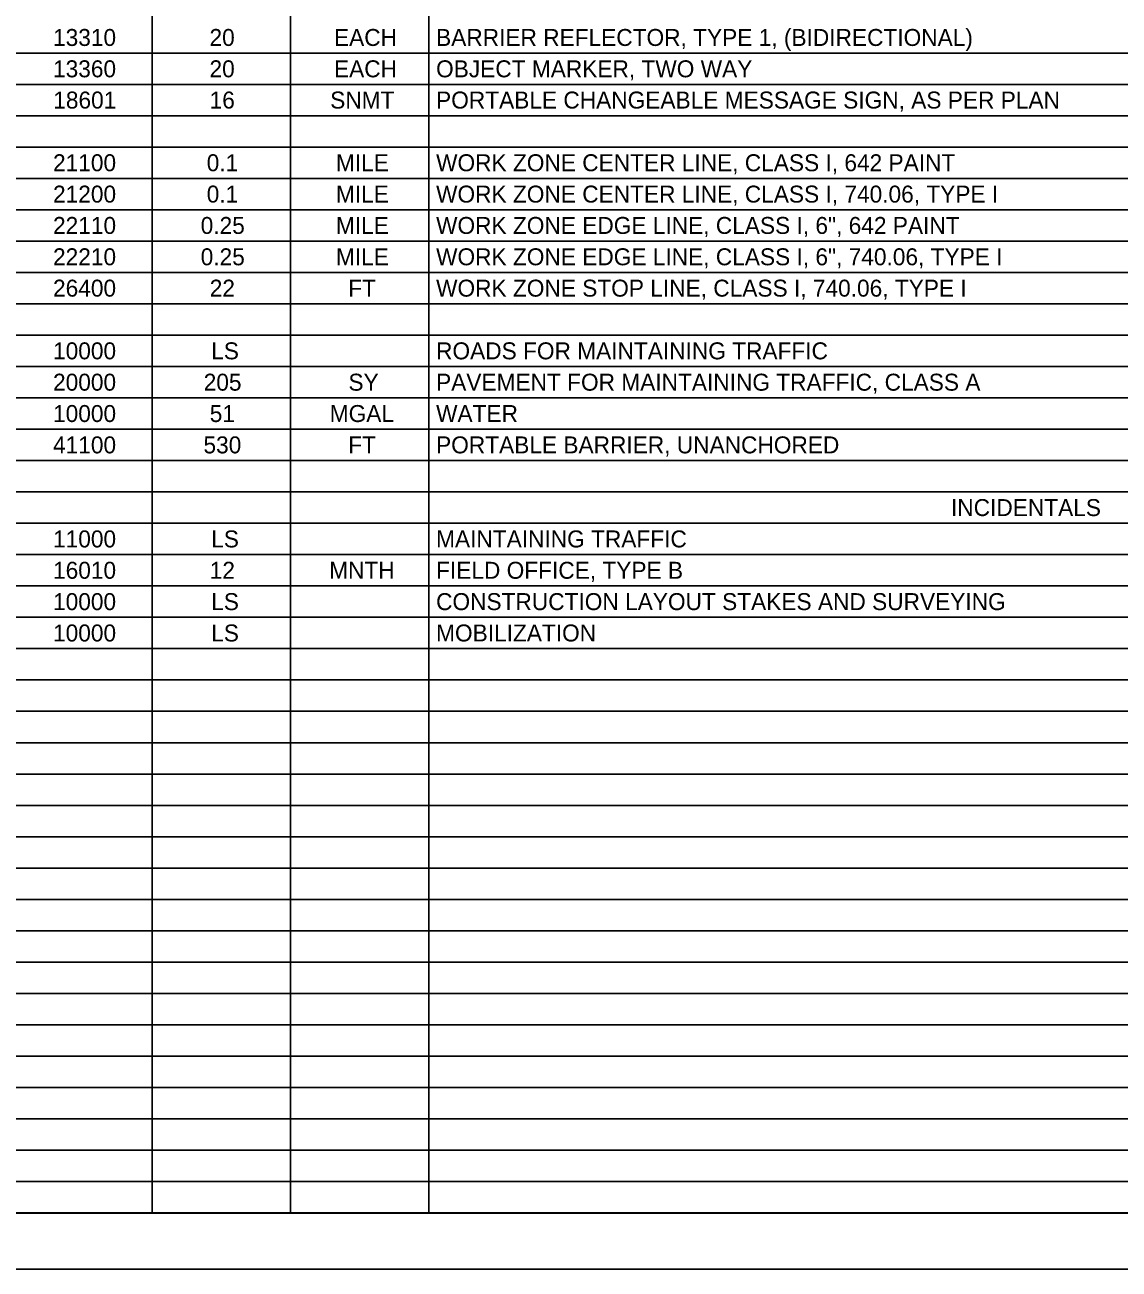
# Model space of a CAD drawing. Extents: x 0 to 34, y 0 to 22.
# Drawn here: x 16.9 to 26.67, y 0 to 11.11 of the extents above; entities that cross this region are included whole.
import ezdxf

# ---------------------------------------------------------------- set-up
doc = ezdxf.new("R2010")
doc.units = 0
for name, color, linetype in [('SH_Border', 7, 'Continuous'), ('SH_Cut_Line', 7, 'Continuous'), ('SH_Text', 7, 'Continuous')]:
    doc.layers.add(name, color=color, linetype=linetype)

msp = doc.modelspace()

# ---------------------------------------------------------------- linework, layer by layer
at = {"layer": 'SH_Border'}
msp.add_lwpolyline([(1.5, 21.5), (33.5, 21.5), (33.5, 0.5), (1.5, 0.5)], close=True, dxfattribs=at)
at = {"layer": 'SH_Cut_Line'}
msp.add_lwpolyline([(0, 0), (34, 0), (34, 22), (0, 22)], close=True, dxfattribs=at)
at = {"layer": 'SH_Text'}
for p, q in [((18.035, 21.5), (18.035, 0.502)), ((19.27, 21.5), (19.27, 0.502)), ((20.505, 21.5), (20.505, 0.502)), ((1.5, 10.861), (32, 10.861)), ((1.5, 10.581), (32, 10.581)), ((1.5, 10.301), (32, 10.301)), ((1.5, 10.021), (32, 10.021)), ((1.5, 9.741), (32, 9.741)), ((1.5, 9.461), (32, 9.461)), ((1.5, 9.181), (32, 9.181)), ((1.5, 8.901), (32, 8.901)), ((1.5, 8.621), (32, 8.621)), ((1.5, 8.342), (32, 8.342)), ((1.5, 8.062), (32, 8.062)), ((1.5, 7.782), (32, 7.782)), ((1.5, 7.502), (32, 7.502)), ((1.5, 7.222), (32, 7.222)), ((1.5, 6.942), (32, 6.942)), ((1.5, 6.662), (32, 6.662)), ((1.5, 6.382), (32, 6.382)), ((1.5, 6.102), (32, 6.102)), ((1.5, 5.822), (32, 5.822)), ((1.5, 5.542), (32, 5.542)), ((1.5, 5.262), (32, 5.262)), ((1.5, 4.982), (32, 4.982)), ((1.5, 4.702), (32, 4.702)), ((1.5, 4.422), (32, 4.422)), ((1.5, 4.142), (32, 4.142)), ((1.5, 3.862), (32, 3.862)), ((1.5, 3.582), (32, 3.582)), ((1.5, 3.302), (32, 3.302)), ((1.5, 3.022), (32, 3.022)), ((1.5, 2.742), (32, 2.742)), ((1.5, 2.462), (32, 2.462)), ((1.5, 2.182), (32, 2.182)), ((1.5, 1.902), (32, 1.902)), ((1.5, 1.622), (32, 1.622)), ((1.5, 1.342), (32, 1.342)), ((1.5, 1.062), (32, 1.062)), ((1.5, 0.782), (32, 0.782)), ((1.5, 0.502), (32, 0.502))]:
    msp.add_line(p, q, dxfattribs=at)

# ---------------------------------------------------------------- texts
for s, height, p in [('13310', 0.1515, (17.149, 10.925)), ('20', 0.1515, (18.547, 10.925)), ('EACH', 0.1515, (19.659, 10.925)), ('BARRIER REFLECTOR, TYPE 1, (BIDIRECTIONAL)', 0.15151, (20.571, 10.925)), ('13360', 0.1515, (17.149, 10.645)), ('20', 0.1515, (18.547, 10.645)), ('EACH', 0.1515, (19.659, 10.645)), ('OBJECT MARKER, TWO WAY', 0.15151, (20.571, 10.645)), ('18601', 0.1515, (17.151, 10.366)), ('16', 0.1515, (18.548, 10.366)), ('SNMT', 0.1515, (19.625, 10.366)), ('PORTABLE CHANGEABLE MESSAGE SIGN, AS PER PLAN', 0.15151, (20.571, 10.366)), ('21100', 0.1515, (17.149, 9.806)), ('0.1', 0.1515, (18.522, 9.806)), ('MILE', 0.1515, (19.676, 9.806)), ('WORK ZONE CENTER LINE, CLASS I, 642 PAINT', 0.15151, (20.571, 9.806)), ('21200', 0.1515, (17.149, 9.526)), ('0.1', 0.1515, (18.522, 9.526)), ('MILE', 0.1515, (19.676, 9.526)), ('WORK ZONE CENTER LINE, CLASS I, 740.06, TYPE I', 0.15151, (20.571, 9.526)), ('22110', 0.1515, (17.149, 9.246)), ('0.25', 0.1515, (18.468, 9.246)), ('MILE', 0.1515, (19.676, 9.246)), ('WORK ZONE EDGE LINE, CLASS I, 6", 642 PAINT', 0.15151, (20.571, 9.246)), ('22210', 0.1515, (17.149, 8.966)), ('0.25', 0.1515, (18.468, 8.966)), ('MILE', 0.1515, (19.676, 8.966)), ('WORK ZONE EDGE LINE, CLASS I, 6", 740.06, TYPE I', 0.15151, (20.571, 8.966)), ('26400', 0.1515, (17.149, 8.686)), ('22', 0.1515, (18.549, 8.686)), ('FT', 0.1515, (19.786, 8.686)), ('WORK ZONE STOP LINE, CLASS I, 740.06, TYPE I', 0.15151, (20.571, 8.686)), ('10000', 0.1515, (17.149, 8.126)), ('LS', 0.1515, (18.562, 8.126)), ('ROADS FOR MAINTAINING TRAFFIC', 0.15151, (20.571, 8.126)), ('20000', 0.1515, (17.149, 7.846)), ('205', 0.1515, (18.495, 7.846)), ('SY', 0.1515, (19.788, 7.846)), ('PAVEMENT FOR MAINTAINING TRAFFIC, CLASS A', 0.15151, (20.571, 7.846)), ('10000', 0.1515, (17.149, 7.566)), ('51', 0.1515, (18.549, 7.566)), ('MGAL', 0.1515, (19.621, 7.566)), ('WATER', 0.1515, (20.571, 7.566)), ('41100', 0.1515, (17.149, 7.286)), ('530', 0.1515, (18.493, 7.286)), ('FT', 0.1515, (19.786, 7.286)), ('PORTABLE BARRIER, UNANCHORED', 0.15151, (20.571, 7.286)), ('INCIDENTALS', 0.15151, (25.171, 6.726)), ('11000', 0.1515, (17.149, 6.446)), ('LS', 0.1515, (18.562, 6.446)), ('MAINTAINING TRAFFIC', 0.15151, (20.571, 6.446)), ('16010', 0.1515, (17.149, 6.166)), ('12', 0.1515, (18.549, 6.166)), ('MNTH', 0.1515, (19.616, 6.166)), ('FIELD OFFICE, TYPE B', 0.15151, (20.571, 6.166)), ('10000', 0.1515, (17.149, 5.886)), ('LS', 0.1515, (18.562, 5.886)), ('CONSTRUCTION LAYOUT STAKES AND SURVEYING', 0.15151, (20.571, 5.886)), ('10000', 0.1515, (17.149, 5.606)), ('LS', 0.1515, (18.562, 5.606)), ('MOBILIZATION', 0.15151, (20.571, 5.606))]:
    msp.add_text(s, height=height, dxfattribs=at).set_placement(p)

doc.saveas('drawing.dxf')
